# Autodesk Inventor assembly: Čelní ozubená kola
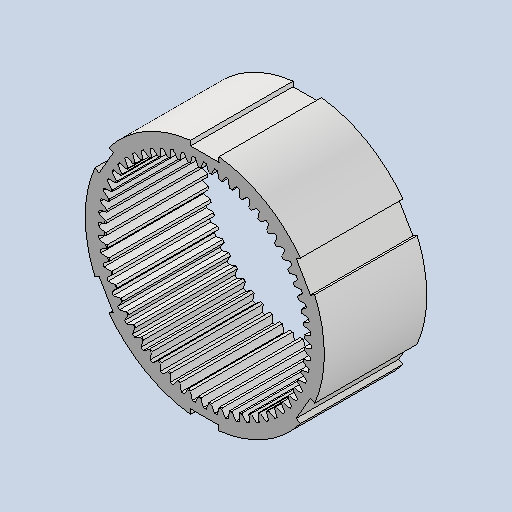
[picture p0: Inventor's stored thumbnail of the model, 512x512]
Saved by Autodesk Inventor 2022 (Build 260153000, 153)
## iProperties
ClientObjectVersion: 1
Created: 2025-05
Part Number: Čelní ozubená kola
Document SubType Name: Assembly
Designer: jbart
Categories: <?xml version="1.0" encoding="UTF-16"?> <MemberInstance><Categories><FamilyTemplate/><ParamToTemplateMap><ParamToTemplate><ParamToTemplate CategoryParameter="//
Author: jbart
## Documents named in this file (2)
- C:\Users\jbart\OneDrive\Dokumenty\Inventor\Převodovka navijáku\Korunové kolo 2\Design Accelerator\Čelní ozubená kola1.iam
- C:\Users\jbart\OneDrive\Dokumenty\Inventor\Převodovka navijáku\Korunové kolo 2\Design Accelerator\Čelní ozubené kolo21.ipt
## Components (1 placed, 1 different names)
1. Čelní ozubené kolo2:1
